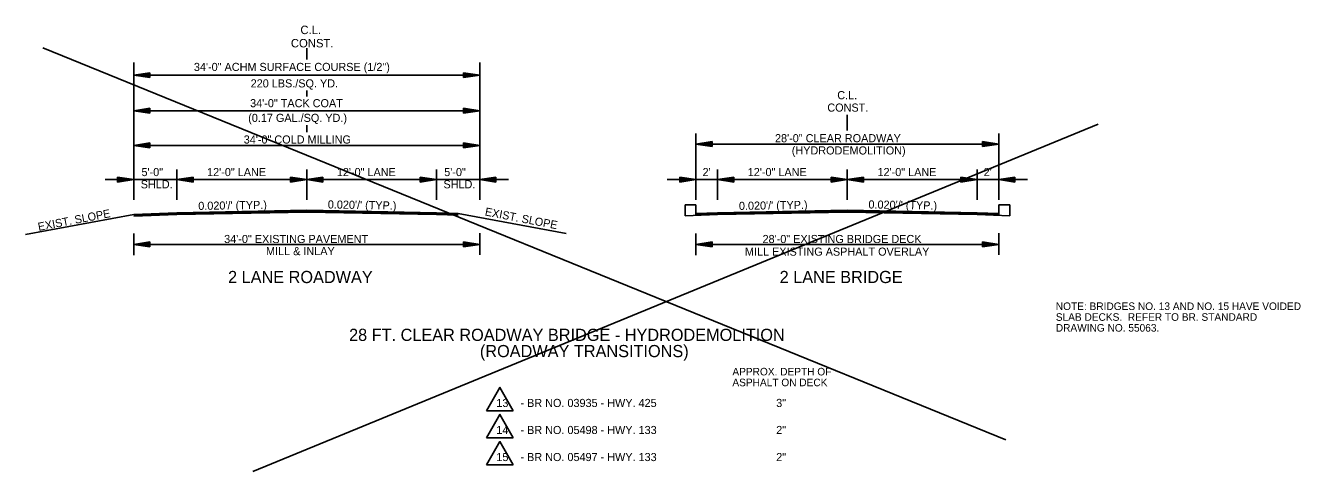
# Model space of a CAD drawing. Extents: x 549600 to 1930787, y -1955432 to 596640.
# Drawn here: x 549600 to 550780, y -1948624 to -1948212 of the extents above; entities that cross this region are included whole.
import ezdxf

# ---------------------------------------------------------------- set-up
doc = ezdxf.new("R2010")
doc.units = 0
for name, color, linetype in [('R_Border', 7, 'Continuous'), ('R_Border Notes', 7, 'Continuous'), ('S_AREA_CALC', 7, 'Continuous')]:
    doc.layers.add(name, color=color, linetype=linetype)

msp = doc.modelspace()

# ---------------------------------------------------------------- linework, layer by layer
at = {"layer": 'R_Border'}
for p, q in [((550507.2, -1948594.5), (549616.5, -1948232.2)), ((550592.6, -1948302.9), (549810.8, -1948623.9)), ((550360.5, -1948294.2), (550360.5, -1948308.7)), ((550210.4, -1948377.3), (550210.4, -1948387.4)), ((550220.5, -1948377.3), (550210.4, -1948377.3)), ((550220.5, -1948386.7), (550220.5, -1948377.3)), ((550500.5, -1948386.7), (550500.5, -1948377.3)), ((550500.5, -1948377.3), (550510.7, -1948377.3)), ((550510.7, -1948377.3), (550510.7, -1948387.4)), ((550026.8, -1948567.7), (550051.6, -1948567.7)), ((550026.8, -1948592.7), (550051.6, -1948592.7)), ((550026.8, -1948617.7), (550051.6, -1948617.7))]:
    msp.add_line(p, q, dxfattribs=at)
for points in [[(550051.6, -1948567.7), (550039.2, -1948546.2), (550026.8, -1948567.7)], [(550051.6, -1948592.7), (550039.2, -1948571.2), (550026.8, -1948592.7)], [(550051.6, -1948617.7), (550039.2, -1948596.2), (550026.8, -1948617.7)]]:
    msp.add_lwpolyline(points, dxfattribs=at)
at = {"layer": 'S_AREA_CALC'}
for p, q in [((549860.5, -1948242.9), (549860.5, -1948232.6)), ((549700.5, -1948372.8), (549700.5, -1948245.7)), ((550020.5, -1948372.8), (550020.5, -1948245.7)), ((549715.5, -1948255.2), (549700.5, -1948257.4)), ((549700.5, -1948257.4), (550020.5, -1948257.4)), ((549715.5, -1948259.7), (549700.5, -1948257.4)), ((549715.5, -1948255.5), (549703, -1948257.4)), ((549715.5, -1948259.3), (549703, -1948257.4)), ((549715.5, -1948255.9), (549705.6, -1948257.4)), ((549715.5, -1948258.9), (549705.6, -1948257.4)), ((549715.5, -1948256.3), (549708.1, -1948257.4)), ((549715.5, -1948258.5), (549708.1, -1948257.4)), ((549715.5, -1948256.7), (549710.7, -1948257.4)), ((549715.5, -1948258.1), (549710.7, -1948257.4)), ((549715.5, -1948257.1), (549713.2, -1948257.4)), ((549715.5, -1948257.8), (549713.2, -1948257.4)), ((549715.5, -1948259.7), (549715.5, -1948255.2)), ((550005.5, -1948255.2), (550020.5, -1948257.4)), ((550005.5, -1948255.2), (550005.5, -1948259.7)), ((550005.5, -1948255.5), (550018, -1948257.4)), ((550005.5, -1948255.9), (550015.4, -1948257.4)), ((550005.5, -1948256.3), (550013, -1948257.4)), ((550005.5, -1948256.7), (550010.4, -1948257.4)), ((550005.5, -1948257.1), (550007.9, -1948257.4)), ((550005.5, -1948259.7), (550020.5, -1948257.4)), ((550005.5, -1948258.2), (550010.4, -1948257.4)), ((550005.5, -1948258.9), (550015.4, -1948257.4)), ((550005.5, -1948259.3), (550018, -1948257.4)), ((550005.5, -1948258.5), (550013, -1948257.4)), ((550005.5, -1948257.8), (550007.9, -1948257.4)), ((549860.5, -1948277.2), (549860.5, -1948271.6)), ((549715.5, -1948288.1), (549700.5, -1948290.4)), ((549700.5, -1948290.4), (550020.5, -1948290.4)), ((549715.5, -1948292.6), (549700.5, -1948290.4)), ((549715.5, -1948288.5), (549703, -1948290.4)), ((549715.5, -1948292.3), (549703, -1948290.4)), ((549715.5, -1948288.9), (549705.6, -1948290.4)), ((549715.5, -1948291.9), (549705.6, -1948290.4)), ((549715.5, -1948289.3), (549708.1, -1948290.4)), ((549715.5, -1948291.5), (549708.1, -1948290.4)), ((549715.5, -1948289.6), (549710.7, -1948290.4)), ((549715.5, -1948291.1), (549710.7, -1948290.4)), ((549715.5, -1948290), (549713.2, -1948290.4)), ((549715.5, -1948290.7), (549713.2, -1948290.4)), ((549715.5, -1948292.6), (549715.5, -1948288.1)), ((550005.5, -1948288.1), (550020.5, -1948290.4)), ((550005.5, -1948288.1), (550005.5, -1948292.6)), ((550005.5, -1948288.5), (550018, -1948290.4)), ((550005.5, -1948288.9), (550015.4, -1948290.4)), ((550005.5, -1948289.3), (550013, -1948290.4)), ((550005.5, -1948289.7), (550010.4, -1948290.4)), ((550005.5, -1948290), (550007.9, -1948290.4)), ((550005.5, -1948292.6), (550020.5, -1948290.4)), ((550005.5, -1948291.1), (550010.4, -1948290.4)), ((550005.5, -1948291.9), (550015.4, -1948290.4)), ((550005.5, -1948292.3), (550018, -1948290.4)), ((550005.5, -1948291.5), (550013, -1948290.4)), ((550005.5, -1948290.7), (550007.9, -1948290.4)), ((549860.5, -1948310.1), (549860.5, -1948303.7)), ((550220.5, -1948372.8), (550220.5, -1948311.3)), ((550500.5, -1948372.8), (550500.5, -1948311.3)), ((549715.5, -1948320.1), (549700.5, -1948322.4)), ((549700.5, -1948322.4), (550020.5, -1948322.4)), ((549715.5, -1948324.6), (549700.5, -1948322.4)), ((549715.5, -1948320.5), (549703, -1948322.4)), ((549715.5, -1948324.2), (549703, -1948322.4)), ((549715.5, -1948320.9), (549705.6, -1948322.4)), ((549715.5, -1948323.8), (549705.6, -1948322.4)), ((549715.5, -1948321.2), (549708.1, -1948322.4)), ((549715.5, -1948323.5), (549708.1, -1948322.4)), ((549715.5, -1948321.6), (549710.7, -1948322.4)), ((549715.5, -1948323.1), (549710.7, -1948322.4)), ((549715.5, -1948322), (549713.2, -1948322.4)), ((549715.5, -1948322.7), (549713.2, -1948322.4)), ((549715.5, -1948324.6), (549715.5, -1948320.1)), ((550005.5, -1948320.1), (550020.5, -1948322.4)), ((550005.5, -1948320.1), (550005.5, -1948324.6)), ((550005.5, -1948320.5), (550018, -1948322.4)), ((550005.5, -1948320.9), (550015.4, -1948322.4)), ((550005.5, -1948321.2), (550013, -1948322.4)), ((550005.5, -1948321.6), (550010.4, -1948322.4)), ((550005.5, -1948322), (550007.9, -1948322.4)), ((550005.5, -1948324.6), (550020.5, -1948322.4)), ((550005.5, -1948323.1), (550010.4, -1948322.4)), ((550005.5, -1948323.8), (550015.4, -1948322.4)), ((550005.5, -1948324.2), (550018, -1948322.4)), ((550005.5, -1948323.5), (550013, -1948322.4)), ((550005.5, -1948322.7), (550007.9, -1948322.4)), ((550235.5, -1948318.9), (550220.5, -1948321.2)), ((550500.5, -1948321.2), (550220.5, -1948321.2)), ((550235.5, -1948323.4), (550220.5, -1948321.2)), ((550235.5, -1948319.3), (550223, -1948321.2)), ((550235.5, -1948323.1), (550223, -1948321.2)), ((550235.5, -1948319.7), (550225.6, -1948321.2)), ((550235.5, -1948322.7), (550225.6, -1948321.2)), ((550235.5, -1948320.1), (550228.1, -1948321.2)), ((550235.5, -1948322.3), (550228.1, -1948321.2)), ((550235.5, -1948320.5), (550230.7, -1948321.2)), ((550235.5, -1948321.9), (550230.7, -1948321.2)), ((550235.5, -1948320.8), (550233.2, -1948321.2)), ((550235.5, -1948321.5), (550233.2, -1948321.2)), ((550235.5, -1948318.9), (550235.5, -1948323.4)), ((550485.5, -1948318.9), (550500.5, -1948321.2)), ((550485.5, -1948323.4), (550485.5, -1948318.9)), ((550485.5, -1948319.3), (550498, -1948321.2)), ((550485.5, -1948319.7), (550495.4, -1948321.2)), ((550485.5, -1948320.1), (550493, -1948321.2)), ((550485.5, -1948320.4), (550490.4, -1948321.2)), ((550485.5, -1948320.8), (550487.9, -1948321.2)), ((550485.5, -1948323.4), (550500.5, -1948321.2)), ((550485.5, -1948321.9), (550490.4, -1948321.2)), ((550485.5, -1948322.7), (550495.4, -1948321.2)), ((550485.5, -1948323.1), (550498, -1948321.2)), ((550485.5, -1948322.3), (550493, -1948321.2)), ((550485.5, -1948321.5), (550487.9, -1948321.2)), ((549685.5, -1948351.8), (549700.5, -1948354)), ((549685.5, -1948351.8), (549685.5, -1948356.3)), ((549685.5, -1948352.1), (549698, -1948354)), ((549740.5, -1948372.8), (549740.5, -1948344.8)), ((549755.5, -1948351.8), (549740.5, -1948354)), ((549755.5, -1948352.1), (549743, -1948354)), ((549755.5, -1948351.8), (549755.5, -1948356.3)), ((549845.5, -1948351.8), (549860.5, -1948354)), ((549845.5, -1948351.8), (549845.5, -1948356.3)), ((549845.5, -1948352.1), (549858, -1948354)), ((549860.5, -1948372.8), (549860.5, -1948344.8)), ((549875.5, -1948351.8), (549860.5, -1948354)), ((549875.5, -1948352.1), (549863, -1948354)), ((549875.5, -1948351.8), (549875.5, -1948356.3)), ((549965.5, -1948351.8), (549980.5, -1948354)), ((549965.5, -1948351.8), (549965.5, -1948356.3)), ((549965.5, -1948352.1), (549978, -1948354)), ((549980.5, -1948372.8), (549980.5, -1948344.8)), ((550035.5, -1948351.8), (550020.5, -1948354)), ((550035.5, -1948352.1), (550023, -1948354)), ((550035.5, -1948351.8), (550035.5, -1948356.3)), ((550205.5, -1948351.8), (550220.5, -1948354)), ((550205.5, -1948351.8), (550205.5, -1948356.3)), ((550205.5, -1948352.1), (550218, -1948354)), ((550240.5, -1948372.8), (550240.5, -1948344.8)), ((550255.5, -1948351.8), (550240.5, -1948354)), ((550255.5, -1948352.1), (550243, -1948354)), ((550255.5, -1948351.8), (550255.5, -1948356.3)), ((550345.5, -1948351.8), (550360.5, -1948354)), ((550345.5, -1948351.8), (550345.5, -1948356.3)), ((550345.5, -1948352.1), (550358, -1948354)), ((550360.5, -1948372.8), (550360.5, -1948344.8)), ((550375.5, -1948351.8), (550360.5, -1948354)), ((550375.5, -1948352.1), (550363, -1948354)), ((550375.5, -1948351.8), (550375.5, -1948356.3)), ((550465.5, -1948351.8), (550480.5, -1948354)), ((550465.5, -1948351.8), (550465.5, -1948356.3)), ((550465.5, -1948352.1), (550478, -1948354)), ((550480.5, -1948372.8), (550480.5, -1948344.8)), ((550515.5, -1948351.8), (550500.5, -1948354)), ((550515.5, -1948352.1), (550503, -1948354)), ((550515.5, -1948351.8), (550515.5, -1948356.3)), ((549700.5, -1948354), (549674, -1948354)), ((549685.5, -1948352.5), (549695.4, -1948354)), ((549685.5, -1948352.9), (549693, -1948354)), ((549685.5, -1948353.3), (549690.4, -1948354)), ((549685.5, -1948353.7), (549687.9, -1948354)), ((549685.5, -1948356.3), (549700.5, -1948354)), ((549685.5, -1948354.8), (549690.4, -1948354)), ((549685.5, -1948355.5), (549695.4, -1948354)), ((549685.5, -1948355.9), (549698, -1948354)), ((549685.5, -1948355.1), (549693, -1948354)), ((549685.5, -1948354.4), (549687.9, -1948354)), ((549740.5, -1948354), (549700.5, -1948354)), ((549860.5, -1948354), (549740.5, -1948354)), ((549755.5, -1948356.3), (549740.5, -1948354)), ((549755.5, -1948355.9), (549743, -1948354)), ((549755.5, -1948352.5), (549745.6, -1948354)), ((549755.5, -1948355.5), (549745.6, -1948354)), ((549755.5, -1948352.9), (549748.1, -1948354)), ((549755.5, -1948355.1), (549748.1, -1948354)), ((549755.5, -1948353.3), (549750.7, -1948354)), ((549755.5, -1948354.8), (549750.7, -1948354)), ((549755.5, -1948353.7), (549753.2, -1948354)), ((549755.5, -1948354.4), (549753.2, -1948354)), ((549845.5, -1948352.5), (549855.4, -1948354)), ((549845.5, -1948352.9), (549853, -1948354)), ((549845.5, -1948353.3), (549850.4, -1948354)), ((549845.5, -1948353.7), (549847.9, -1948354)), ((549845.5, -1948356.3), (549860.5, -1948354)), ((549845.5, -1948354.8), (549850.4, -1948354)), ((549845.5, -1948355.5), (549855.4, -1948354)), ((549845.5, -1948355.9), (549858, -1948354)), ((549845.5, -1948355.1), (549853, -1948354)), ((549845.5, -1948354.4), (549847.9, -1948354)), ((549980.5, -1948354), (549860.5, -1948354)), ((549875.5, -1948356.3), (549860.5, -1948354)), ((549875.5, -1948355.9), (549863, -1948354)), ((549875.5, -1948352.5), (549865.6, -1948354)), ((549875.5, -1948355.5), (549865.6, -1948354)), ((549875.5, -1948352.9), (549868.1, -1948354)), ((549875.5, -1948355.1), (549868.1, -1948354)), ((549875.5, -1948353.3), (549870.7, -1948354)), ((549875.5, -1948354.8), (549870.7, -1948354)), ((549875.5, -1948353.7), (549873.2, -1948354)), ((549875.5, -1948354.4), (549873.2, -1948354)), ((549965.5, -1948352.5), (549975.4, -1948354)), ((549965.5, -1948352.9), (549973, -1948354)), ((549965.5, -1948353.3), (549970.4, -1948354)), ((549965.5, -1948353.7), (549967.9, -1948354)), ((549965.5, -1948356.3), (549980.5, -1948354)), ((549965.5, -1948354.8), (549970.4, -1948354)), ((549965.5, -1948355.5), (549975.4, -1948354)), ((549965.5, -1948355.9), (549978, -1948354)), ((549965.5, -1948355.1), (549973, -1948354)), ((549965.5, -1948354.4), (549967.9, -1948354)), ((549980.5, -1948354), (550020.5, -1948354)), ((550035.5, -1948356.3), (550020.5, -1948354)), ((550047.1, -1948354), (550020.5, -1948354)), ((550035.5, -1948355.9), (550023, -1948354)), ((550035.5, -1948352.5), (550025.6, -1948354)), ((550035.5, -1948355.5), (550025.6, -1948354)), ((550035.5, -1948352.9), (550028.1, -1948354)), ((550035.5, -1948355.1), (550028.1, -1948354)), ((550035.5, -1948353.3), (550030.7, -1948354)), ((550035.5, -1948354.8), (550030.7, -1948354)), ((550035.5, -1948353.7), (550033.2, -1948354)), ((550035.5, -1948354.4), (550033.2, -1948354)), ((550220.5, -1948354), (550194, -1948354)), ((550205.5, -1948352.5), (550215.4, -1948354)), ((550205.5, -1948352.9), (550213, -1948354)), ((550205.5, -1948353.3), (550210.4, -1948354)), ((550205.5, -1948353.7), (550207.9, -1948354)), ((550205.5, -1948356.3), (550220.5, -1948354)), ((550205.5, -1948354.8), (550210.4, -1948354)), ((550205.5, -1948355.5), (550215.4, -1948354)), ((550205.5, -1948355.9), (550218, -1948354)), ((550205.5, -1948355.1), (550213, -1948354)), ((550205.5, -1948354.4), (550207.9, -1948354)), ((550240.5, -1948354), (550220.5, -1948354)), ((550360.5, -1948354), (550240.5, -1948354)), ((550255.5, -1948356.3), (550240.5, -1948354)), ((550255.5, -1948355.9), (550243, -1948354)), ((550255.5, -1948352.5), (550245.6, -1948354)), ((550255.5, -1948355.5), (550245.6, -1948354)), ((550255.5, -1948352.9), (550248.1, -1948354)), ((550255.5, -1948355.1), (550248.1, -1948354)), ((550255.5, -1948353.3), (550250.7, -1948354)), ((550255.5, -1948354.8), (550250.7, -1948354)), ((550255.5, -1948353.7), (550253.2, -1948354)), ((550255.5, -1948354.4), (550253.2, -1948354)), ((550345.5, -1948352.5), (550355.4, -1948354)), ((550345.5, -1948352.9), (550353, -1948354)), ((550345.5, -1948353.3), (550350.4, -1948354)), ((550345.5, -1948353.7), (550347.9, -1948354)), ((550345.5, -1948356.3), (550360.5, -1948354)), ((550345.5, -1948354.8), (550350.4, -1948354)), ((550345.5, -1948355.5), (550355.4, -1948354)), ((550345.5, -1948355.9), (550358, -1948354)), ((550345.5, -1948355.1), (550353, -1948354)), ((550345.5, -1948354.4), (550347.9, -1948354)), ((550480.5, -1948354), (550360.5, -1948354)), ((550375.5, -1948356.3), (550360.5, -1948354)), ((550375.5, -1948355.9), (550363, -1948354)), ((550375.5, -1948352.5), (550365.6, -1948354)), ((550375.5, -1948355.5), (550365.6, -1948354)), ((550375.5, -1948352.9), (550368.1, -1948354)), ((550375.5, -1948355.1), (550368.1, -1948354)), ((550375.5, -1948353.3), (550370.7, -1948354)), ((550375.5, -1948354.8), (550370.7, -1948354)), ((550375.5, -1948353.7), (550373.2, -1948354)), ((550375.5, -1948354.4), (550373.2, -1948354)), ((550465.5, -1948352.5), (550475.4, -1948354)), ((550465.5, -1948352.9), (550473, -1948354)), ((550465.5, -1948353.3), (550470.4, -1948354)), ((550465.5, -1948353.7), (550467.9, -1948354)), ((550465.5, -1948356.3), (550480.5, -1948354)), ((550465.5, -1948354.8), (550470.4, -1948354)), ((550465.5, -1948355.5), (550475.4, -1948354)), ((550465.5, -1948355.9), (550478, -1948354)), ((550465.5, -1948355.1), (550473, -1948354)), ((550465.5, -1948354.4), (550467.9, -1948354)), ((550480.5, -1948354), (550500.5, -1948354)), ((550515.5, -1948356.3), (550500.5, -1948354)), ((550527.1, -1948354), (550500.5, -1948354)), ((550515.5, -1948355.9), (550503, -1948354)), ((550515.5, -1948352.5), (550505.6, -1948354)), ((550515.5, -1948355.5), (550505.6, -1948354)), ((550515.5, -1948352.9), (550508.1, -1948354)), ((550515.5, -1948355.1), (550508.1, -1948354)), ((550515.5, -1948353.3), (550510.7, -1948354)), ((550515.5, -1948354.8), (550510.7, -1948354)), ((550515.5, -1948353.7), (550513.2, -1948354)), ((550515.5, -1948354.4), (550513.2, -1948354)), ((549700.5, -1948386.3), (549600.5, -1948404.7)), ((549740.5, -1948384.7), (549700.5, -1948386.3)), ((549740.5, -1948385), (549700.5, -1948386.6)), ((549740.5, -1948385.3), (549700.5, -1948386.9)), ((549740.5, -1948385.6), (549700.5, -1948387.2)), ((549740.5, -1948385.9), (549700.5, -1948387.5)), ((549740.5, -1948386.2), (549700.5, -1948387.8)), ((549860.5, -1948382.3), (549740.5, -1948384.7)), ((549860.5, -1948382.6), (549740.5, -1948385)), ((549860.5, -1948382.9), (549740.5, -1948385.3)), ((549860.5, -1948383.2), (549740.5, -1948385.6)), ((549860.5, -1948383.5), (549740.5, -1948385.9)), ((549860.5, -1948383.8), (549740.5, -1948386.2)), ((549860.5, -1948384), (549740.5, -1948386.4)), ((549860.5, -1948382.3), (549980.5, -1948384.7)), ((549860.5, -1948382.6), (549980.5, -1948385)), ((549860.5, -1948382.9), (549980.5, -1948385.3)), ((549860.5, -1948383.2), (549980.5, -1948385.6)), ((549860.5, -1948383.5), (549980.5, -1948385.9)), ((549860.5, -1948383.8), (549980.5, -1948386.2)), ((549860.5, -1948384), (549980.5, -1948386.4)), ((549980.5, -1948384.7), (550000.5, -1948385.5)), ((549980.5, -1948385), (550000.5, -1948385.8)), ((549980.5, -1948385.3), (550000.5, -1948386.1)), ((549980.5, -1948385.6), (550000.5, -1948386.4)), ((549980.5, -1948385.9), (550000.5, -1948386.7)), ((549980.5, -1948386.2), (550000.5, -1948387)), ((550000.5, -1948385.5), (550100.6, -1948403.9)), ((550240.5, -1948386.2), (550210.4, -1948387.4)), ((550240.5, -1948384.7), (550220.5, -1948385.5)), ((550240.5, -1948385), (550220.5, -1948385.8)), ((550240.5, -1948385.3), (550220.5, -1948386.1)), ((550240.5, -1948385.6), (550220.5, -1948386.4)), ((550240.5, -1948385.9), (550220.5, -1948386.7)), ((550360.5, -1948382.3), (550240.5, -1948384.7)), ((550360.5, -1948382.6), (550240.5, -1948385)), ((550360.5, -1948382.9), (550240.5, -1948385.3)), ((550360.5, -1948383.2), (550240.5, -1948385.6)), ((550360.5, -1948383.5), (550240.5, -1948385.9)), ((550360.5, -1948383.8), (550240.5, -1948386.2)), ((550360.5, -1948384), (550240.5, -1948386.4)), ((550360.5, -1948382.3), (550480.5, -1948384.7)), ((550360.5, -1948382.6), (550480.5, -1948385)), ((550360.5, -1948382.9), (550480.5, -1948385.3)), ((550360.5, -1948383.2), (550480.5, -1948385.6)), ((550360.5, -1948383.5), (550480.5, -1948385.9)), ((550360.5, -1948383.8), (550480.5, -1948386.2)), ((550360.5, -1948384), (550480.5, -1948386.4)), ((550480.5, -1948384.7), (550500.5, -1948385.5)), ((550480.5, -1948385), (550500.5, -1948385.8)), ((550480.5, -1948385.3), (550500.5, -1948386.1)), ((550480.5, -1948385.6), (550500.5, -1948386.4)), ((550480.5, -1948385.9), (550500.5, -1948386.7)), ((550480.5, -1948386.2), (550510.7, -1948387.4)), ((549700.5, -1948404), (549700.5, -1948424)), ((550020.5, -1948403.7), (550020.5, -1948423.7)), ((550220.5, -1948404), (550220.5, -1948424)), ((550500.5, -1948403.7), (550500.5, -1948423.7)), ((549715.5, -1948411.7), (549700.5, -1948414)), ((549715.5, -1948416.2), (549700.5, -1948414)), ((550020.5, -1948414), (549700.5, -1948414)), ((549715.5, -1948412.1), (549703, -1948414)), ((549715.5, -1948415.9), (549703, -1948414)), ((549715.5, -1948412.5), (549705.6, -1948414)), ((549715.5, -1948415.5), (549705.6, -1948414)), ((549715.5, -1948412.9), (549708.1, -1948414)), ((549715.5, -1948415.1), (549708.1, -1948414)), ((549715.5, -1948413.3), (549710.7, -1948414)), ((549715.5, -1948414.7), (549710.7, -1948414)), ((549715.5, -1948413.6), (549713.2, -1948414)), ((549715.5, -1948414.3), (549713.2, -1948414)), ((549715.5, -1948411.7), (549715.5, -1948416.2)), ((550005.5, -1948411.7), (550020.5, -1948414)), ((550005.5, -1948416.2), (550005.5, -1948411.7)), ((550005.5, -1948412.1), (550018, -1948414)), ((550005.5, -1948412.5), (550015.4, -1948414)), ((550005.5, -1948412.9), (550013, -1948414)), ((550005.5, -1948413.2), (550010.4, -1948414)), ((550005.5, -1948413.6), (550007.9, -1948414)), ((550005.5, -1948416.2), (550020.5, -1948414)), ((550005.5, -1948414.7), (550010.4, -1948414)), ((550005.5, -1948415.5), (550015.4, -1948414)), ((550005.5, -1948415.9), (550018, -1948414)), ((550005.5, -1948415.1), (550013, -1948414)), ((550005.5, -1948414.3), (550007.9, -1948414)), ((550235.5, -1948411.7), (550220.5, -1948414)), ((550235.5, -1948416.2), (550220.5, -1948414)), ((550500.5, -1948414), (550220.5, -1948414)), ((550235.5, -1948412.1), (550223, -1948414)), ((550235.5, -1948415.9), (550223, -1948414)), ((550235.5, -1948412.5), (550225.6, -1948414)), ((550235.5, -1948415.5), (550225.6, -1948414)), ((550235.5, -1948412.9), (550228.1, -1948414)), ((550235.5, -1948415.1), (550228.1, -1948414)), ((550235.5, -1948413.3), (550230.7, -1948414)), ((550235.5, -1948414.7), (550230.7, -1948414)), ((550235.5, -1948413.6), (550233.2, -1948414)), ((550235.5, -1948414.3), (550233.2, -1948414)), ((550235.5, -1948411.7), (550235.5, -1948416.2)), ((550485.5, -1948411.7), (550500.5, -1948414)), ((550485.5, -1948416.2), (550485.5, -1948411.7)), ((550485.5, -1948412.1), (550498, -1948414)), ((550485.5, -1948412.5), (550495.4, -1948414)), ((550485.5, -1948412.9), (550493, -1948414)), ((550485.5, -1948413.2), (550490.4, -1948414)), ((550485.5, -1948413.6), (550487.9, -1948414)), ((550485.5, -1948416.2), (550500.5, -1948414)), ((550485.5, -1948414.7), (550490.4, -1948414)), ((550485.5, -1948415.5), (550495.4, -1948414)), ((550485.5, -1948415.9), (550498, -1948414)), ((550485.5, -1948415.1), (550493, -1948414)), ((550485.5, -1948414.3), (550487.9, -1948414))]:
    msp.add_line(p, q, dxfattribs=at)

# ---------------------------------------------------------------- texts
at = {"layer": 'R_Border'}
for s, height, p in [('C.L.', 7.5, (550351.2, -1948279.7)), ('CONST.', 7.5, (550342, -1948291.2)), ('28 FT. CLEAR ROADWAY BRIDGE - HYDRODEMOLITION', 11.25, (549899.7, -1948503.2)), ('(ROADWAY TRANSITIONS)', 11.25, (550020.7, -1948518.2)), ('13', 7.5, (550035.9, -1948564.3)), ('- BR NO. 03935 - HWY. 425', 7.5, (550058.2, -1948564.3)), ('3"', 7.5, (550294.7, -1948564.3)), ('14', 7.5, (550035.9, -1948589.3)), ('- BR NO. 05498 - HWY. 133', 7.5, (550058.2, -1948589.3)), ('2"', 7.5, (550294.7, -1948589.3)), ('15', 7.5, (550035.9, -1948614.3)), ('- BR NO. 05497 - HWY. 133', 7.5, (550058.2, -1948614.3)), ('2"', 7.5, (550294.7, -1948614.3))]:
    msp.add_text(s, height=height, dxfattribs=at).set_placement(p)
at = {"layer": 'R_Border Notes'}
for s, p in [('NOTE: BRIDGES NO. 13 AND NO. 15 HAVE VOIDED', (550553.3, -1948474.6)), ('SLAB DECKS.  REFER TO BR. STANDARD', (550553.3, -1948484.6)), ('DRAWING NO. 55063.', (550553.3, -1948494.6)), ('APPROX. DEPTH OF', (550254.2, -1948535.1)), ('ASPHALT ON DECK', (550254.2, -1948545.1))]:
    msp.add_text(s, height=7, dxfattribs=at).set_placement(p)
at = {"layer": 'S_AREA_CALC'}
for s, height, p in [('C.L.', 7.8, (549854.7, -1948219.5)), ('CONST.', 7.8, (549845.9, -1948231.8)), ('34\'-0" ACHM SURFACE COURSE (1/2")', 7.5, (549756.2, -1948253.6)), ('220 LBS./SQ. YD. ', 7.5, (549808.7, -1948268.8)), ('34\'-0" TACK COAT', 7.5, (549808.2, -1948287.1)), ('(0.17 GAL./SQ. YD.)', 7.5, (549806.4, -1948300.7)), ('34\'-0" COLD MILLING ', 7.5, (549802.3, -1948320.7)), ('28\'-0" CLEAR ROADWAY', 7.5, (550293.6, -1948319.5)), ('(HYDRODEMOLITION)', 7.5, (550309.1, -1948330.8)), ('5\'-0"', 7.5, (549707.7, -1948350.8)), ('12\'-0" LANE', 7.5, (549768.4, -1948350.8)), ('12\'-0" LANE', 7.5, (549888.4, -1948350.8)), ('5\'-0"', 7.5, (549987.7, -1948350.8)), ("2'", 7.5, (550226.6, -1948350.8)), ('12\'-0" LANE', 7.5, (550268.4, -1948350.8)), ('12\'-0" LANE', 7.5, (550388.4, -1948350.8)), ("2'", 7.5, (550486.6, -1948350.8)), ('SHLD.', 7.5, (549707, -1948362.1)), ('SHLD.', 7.5, (549987, -1948362.1)), ('34\'-0" EXISTING PAVEMENT', 7.5, (549784.2, -1948412.7)), ('28\'-0" EXISTING BRIDGE DECK', 7.5, (550282.1, -1948412.7)), ('MILL & INLAY', 7.5, (549822.9, -1948423.9)), ('MILL EXISTING ASPHALT OVERLAY', 7.5, (550265.8, -1948424.4)), ('2 LANE ROADWAY', 11.25, (549787.8, -1948449.7)), ('2 LANE BRIDGE', 11.25, (550297.9, -1948449.7))]:
    msp.add_text(s, height=height, dxfattribs=at).set_placement(p)
for s, rotation, p in [("0.020'/' (TYP.)", 0.9719, (549760.3, -1948382.1)), ("0.020'/' (TYP.)", 359.0281, (549880, -1948380.7)), ("0.020'/' (TYP.)", 0.9719, (550260.3, -1948382.1)), ("0.020'/' (TYP.)", 359.0281, (550380, -1948380.7)), ('EXIST. SLOPE', 10.8829, (549612.7, -1948401.5)), ('EXIST. SLOPE', 349.1171, (550024.9, -1948387.1))]:
    msp.add_text(s, height=7.5, rotation=rotation, dxfattribs=at).set_placement(p)

doc.saveas('drawing.dxf')
